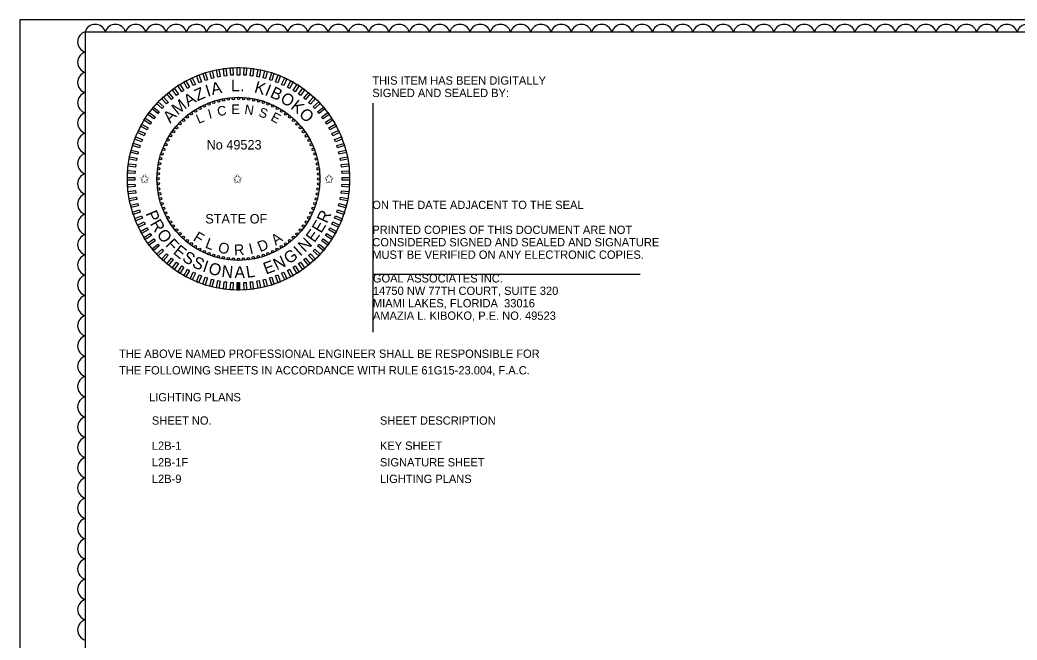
# Model space of a CAD drawing. Extents: x -816.9 to -790.1, y -2199.5 to -2188.9.
# Drawn here: x -811.34 to -802.91, y -2194.13 to -2188.9 of the extents above; entities that cross this region are included whole.
import ezdxf

# ---------------------------------------------------------------- set-up
doc = ezdxf.new("R2010")
doc.units = 0
for name, color, linetype in [('Cloud_dp', 7, 'Continuous'), ('Logo_dp', 7, 'Continuous'), ('NonPlottingEle_dp', 7, 'Continuous'), ('PlotBorder_dp', 7, 'Continuous'), ('ScratchEle_dp', 7, 'Continuous'), ('SheetBorder_dp', 7, 'Continuous'), ('TextMisc', 7, 'Continuous'), ('TextNotes', 7, 'Continuous')]:
    doc.layers.add(name, color=color, linetype=linetype)

msp = doc.modelspace()

# ---------------------------------------------------------------- linework, layer by layer
at = {"layer": 'Cloud_dp'}
for centre, start, end in [((-810.7002, -2189.0276), 17.5, 162.5), ((-810.5291, -2189.0276), 17.5, 162.5), ((-810.358, -2189.0276), 17.5, 162.5), ((-810.1868, -2189.0276), 17.5, 162.5), ((-810.0157, -2189.0276), 17.5, 162.5), ((-809.8446, -2189.0276), 17.5, 162.5), ((-809.6735, -2189.0276), 17.5, 162.5), ((-809.5024, -2189.0276), 17.5, 162.5), ((-809.3312, -2189.0276), 17.5, 162.5), ((-809.1601, -2189.0276), 17.5, 162.5), ((-808.989, -2189.0276), 17.5, 162.5), ((-808.8179, -2189.0276), 17.5, 162.5), ((-808.6467, -2189.0276), 17.5, 162.5), ((-808.4756, -2189.0276), 17.5, 162.5), ((-808.3045, -2189.0276), 17.5, 162.5), ((-808.1334, -2189.0276), 17.5, 162.5), ((-807.9622, -2189.0276), 17.5, 162.5), ((-807.7911, -2189.0276), 17.5, 162.5), ((-807.62, -2189.0276), 17.5, 162.5), ((-807.4489, -2189.0276), 17.5, 162.5), ((-807.2778, -2189.0276), 17.5, 162.5), ((-807.1066, -2189.0276), 17.5, 162.5), ((-806.9355, -2189.0276), 17.5, 162.5), ((-806.7644, -2189.0276), 17.5, 162.5), ((-806.5933, -2189.0276), 17.5, 162.5), ((-806.4221, -2189.0276), 17.5, 162.5), ((-806.251, -2189.0276), 17.5, 162.5), ((-806.0799, -2189.0276), 17.5, 162.5), ((-805.9088, -2189.0276), 17.5, 162.5), ((-805.7377, -2189.0276), 17.5, 162.5), ((-805.5665, -2189.0276), 17.5, 162.5), ((-805.3954, -2189.0276), 17.5, 162.5), ((-805.2243, -2189.0276), 17.5, 162.5), ((-805.0532, -2189.0276), 17.5, 162.5), ((-804.882, -2189.0276), 17.5, 162.5), ((-804.7109, -2189.0276), 17.5, 162.5), ((-804.5398, -2189.0276), 17.5, 162.5), ((-804.3687, -2189.0276), 17.5, 162.5), ((-804.1976, -2189.0276), 17.5, 162.5), ((-804.0264, -2189.0276), 17.5, 162.5), ((-803.8553, -2189.0276), 17.5, 162.5), ((-803.6842, -2189.0276), 17.5, 162.5), ((-803.5131, -2189.0276), 17.5, 162.5), ((-803.3419, -2189.0276), 17.5, 162.5), ((-803.1708, -2189.0276), 17.5, 162.5), ((-802.9997, -2189.0276), 17.5, 162.5), ((-802.8286, -2189.0276), 17.5, 162.5), ((-810.7588, -2189.0862), 107.5, 252.5), ((-810.7588, -2189.2573), 107.5, 252.5), ((-810.7588, -2189.4284), 107.5, 252.5), ((-810.7588, -2189.5996), 107.5, 252.5), ((-810.7588, -2189.7707), 107.5, 252.5), ((-810.7588, -2189.9418), 107.5, 252.5), ((-810.7588, -2190.1129), 107.5, 252.5), ((-810.7588, -2190.2841), 107.5, 252.5), ((-810.7588, -2190.4552), 107.5, 252.5), ((-810.7588, -2190.6263), 107.5, 252.5), ((-810.7588, -2190.7974), 107.5, 252.5), ((-810.7588, -2190.9685), 107.5, 252.5), ((-810.7588, -2191.1397), 107.5, 252.5), ((-810.7588, -2191.3108), 107.5, 252.5), ((-810.7588, -2191.4819), 107.5, 252.5), ((-810.7588, -2191.653), 107.5, 252.5), ((-810.7588, -2191.8242), 107.5, 252.5), ((-810.7588, -2191.9953), 107.5, 252.5), ((-810.7588, -2192.1664), 107.5, 252.5), ((-810.7588, -2192.3375), 107.5, 252.5), ((-810.7588, -2192.5087), 107.5, 252.5), ((-810.7588, -2192.6798), 107.5, 252.5), ((-810.7588, -2192.8509), 107.5, 252.5), ((-810.7588, -2193.022), 107.5, 252.5), ((-810.7588, -2193.1931), 107.5, 252.5), ((-810.7588, -2193.3643), 107.5, 252.5), ((-810.7588, -2193.5354), 107.5, 252.5), ((-810.7588, -2193.7065), 107.5, 252.5), ((-810.7588, -2193.8776), 107.5, 252.5), ((-810.7588, -2194.0488), 107.5, 252.5)]:
    msp.add_arc(centre, 0.0897, start, end, dxfattribs=at)
at = {"layer": 'Logo_dp'}
for p, q in [((-809.5, -2191.1804), (-809.5002, -2191.1179)), ((-809.49, -2191.1804), (-809.4902, -2191.1178)), ((-809.48, -2191.1804), (-809.4802, -2191.1178))]:
    msp.add_line(p, q, dxfattribs=at)
for points in [[(-809.8031, -2189.4233), (-809.8219, -2189.4307), (-809.8449, -2189.3726), (-809.8261, -2189.3652)], [(-809.7511, -2189.4052), (-809.7703, -2189.4115), (-809.7896, -2189.352), (-809.7704, -2189.3458)], [(-809.698, -2189.3905), (-809.7176, -2189.3955), (-809.7332, -2189.335), (-809.7136, -2189.3299)], [(-809.6442, -2189.3791), (-809.664, -2189.3829), (-809.6758, -2189.3215), (-809.6559, -2189.3177)], [(-809.5897, -2189.3711), (-809.6098, -2189.3737), (-809.6176, -2189.3116), (-809.5976, -2189.3091)], [(-809.5349, -2189.3666), (-809.555, -2189.3679), (-809.559, -2189.3055), (-809.5388, -2189.3042)], [(-809.4798, -2189.3655), (-809.5, -2189.3655), (-809.5, -2189.303), (-809.4798, -2189.303)], [(-809.4248, -2189.3679), (-809.445, -2189.3666), (-809.4411, -2189.3042), (-809.4209, -2189.3055)], [(-809.3701, -2189.3737), (-809.3901, -2189.3712), (-809.3823, -2189.3091), (-809.3623, -2189.3117)], [(-809.3158, -2189.3829), (-809.3357, -2189.3792), (-809.324, -2189.3177), (-809.3041, -2189.3215)], [(-809.2623, -2189.3956), (-809.2818, -2189.3905), (-809.2663, -2189.33), (-809.2467, -2189.335)], [(-809.2096, -2189.4115), (-809.2288, -2189.4053), (-809.2095, -2189.3458), (-809.1903, -2189.3521)], [(-809.158, -2189.4308), (-809.1768, -2189.4234), (-809.1538, -2189.3652), (-809.135, -2189.3727)], [(-809.9509, -2189.4964), (-809.968, -2189.5073), (-810.0015, -2189.4545), (-809.9844, -2189.4437)], [(-809.9032, -2189.469), (-809.9209, -2189.4787), (-809.951, -2189.4239), (-809.9333, -2189.4142)], [(-809.8539, -2189.4446), (-809.8721, -2189.4532), (-809.8988, -2189.3966), (-809.8805, -2189.388)], [(-809.1077, -2189.4532), (-809.126, -2189.4446), (-809.0994, -2189.3881), (-809.0811, -2189.3967)], [(-809.059, -2189.4788), (-809.0767, -2189.4691), (-809.0466, -2189.4143), (-809.0289, -2189.424)], [(-809.0119, -2189.5074), (-809.029, -2189.4965), (-808.9955, -2189.4438), (-808.9784, -2189.4546)], [(-810.0407, -2189.5601), (-810.0562, -2189.573), (-810.0961, -2189.5248), (-810.0805, -2189.5119)], [(-809.9968, -2189.5268), (-810.0131, -2189.5387), (-810.0499, -2189.4881), (-810.0335, -2189.4763)], [(-808.9668, -2189.5388), (-808.9831, -2189.527), (-808.9464, -2189.4764), (-808.93, -2189.4883)], [(-808.9237, -2189.5731), (-808.9392, -2189.5602), (-808.8994, -2189.512), (-808.8838, -2189.5249)], [(-810.1217, -2189.6345), (-810.1356, -2189.6492), (-810.1812, -2189.6064), (-810.1673, -2189.5917)], [(-810.0824, -2189.596), (-810.0971, -2189.6098), (-810.1399, -2189.5643), (-810.1252, -2189.5504)], [(-808.8828, -2189.61), (-808.8975, -2189.5961), (-808.8547, -2189.5505), (-808.84, -2189.5644)], [(-808.8443, -2189.6493), (-808.8582, -2189.6346), (-808.8126, -2189.5918), (-808.7988, -2189.6065)], [(-810.1929, -2189.7184), (-810.2048, -2189.7348), (-810.2553, -2189.698), (-810.2435, -2189.6817)], [(-810.1586, -2189.6753), (-810.1715, -2189.6909), (-810.2197, -2189.6511), (-810.2068, -2189.6355)], [(-808.8084, -2189.691), (-808.8213, -2189.6755), (-808.7731, -2189.6356), (-808.7602, -2189.6512)], [(-808.7752, -2189.7349), (-808.7871, -2189.7186), (-808.7365, -2189.6818), (-808.7246, -2189.6982)], [(-810.2529, -2189.8106), (-810.2626, -2189.8284), (-810.3174, -2189.7982), (-810.3077, -2189.7805)], [(-810.2243, -2189.7636), (-810.2352, -2189.7807), (-810.288, -2189.7472), (-810.2771, -2189.7301)], [(-808.7448, -2189.7808), (-808.7556, -2189.7638), (-808.7028, -2189.7303), (-808.692, -2189.7473)], [(-808.7173, -2189.8285), (-808.7271, -2189.8108), (-808.6723, -2189.7807), (-808.6625, -2189.7984)], [(-810.2785, -2189.8594), (-810.2871, -2189.8777), (-810.3436, -2189.8511), (-810.335, -2189.8328)], [(-808.6929, -2189.8779), (-808.7015, -2189.8596), (-808.6449, -2189.8329), (-808.6363, -2189.8512)], [(-810.3202, -2189.9612), (-810.3264, -2189.9805), (-810.3859, -2189.9611), (-810.3796, -2189.9419)], [(-810.3009, -2189.9097), (-810.3084, -2189.9285), (-810.3665, -2189.9054), (-810.359, -2189.8866)], [(-808.6716, -2189.9286), (-808.6791, -2189.9098), (-808.6209, -2189.8868), (-808.6135, -2189.9056)], [(-808.6536, -2189.9806), (-808.6598, -2189.9614), (-808.6004, -2189.9421), (-808.5941, -2189.9613)], [(-810.3361, -2190.0139), (-810.3412, -2190.0335), (-810.4017, -2190.0179), (-810.3967, -2189.9984)], [(-808.6388, -2190.0337), (-808.6439, -2190.0141), (-808.5833, -2189.9985), (-808.5783, -2190.0181)], [(-810.358, -2190.1218), (-810.3605, -2190.1418), (-810.4226, -2190.134), (-810.42, -2190.1139)], [(-810.3488, -2190.0675), (-810.3526, -2190.0873), (-810.414, -2190.0756), (-810.4102, -2190.0558)], [(-808.6275, -2190.0875), (-808.6312, -2190.0677), (-808.5698, -2190.056), (-808.566, -2190.0758)], [(-808.6195, -2190.142), (-808.622, -2190.1219), (-808.56, -2190.1141), (-808.5575, -2190.1342)], [(-810.3638, -2190.1765), (-810.3651, -2190.1967), (-810.4275, -2190.1927), (-810.4262, -2190.1726)], [(-808.6149, -2190.1968), (-808.6162, -2190.1767), (-808.5538, -2190.1727), (-808.5525, -2190.1929)], [(-810.3662, -2190.2315), (-810.3662, -2190.2517), (-810.4287, -2190.2517), (-810.4287, -2190.2315)], [(-810.3651, -2190.2865), (-810.3638, -2190.3067), (-810.4262, -2190.3106), (-810.4275, -2190.2904)], [(-808.6162, -2190.3069), (-808.615, -2190.2867), (-808.5526, -2190.2906), (-808.5538, -2190.3108)], [(-808.6139, -2190.2519), (-808.6139, -2190.2317), (-808.5513, -2190.2317), (-808.5513, -2190.2519)], [(-810.3606, -2190.3414), (-810.358, -2190.3614), (-810.4201, -2190.3693), (-810.4226, -2190.3492)], [(-808.622, -2190.3616), (-808.6195, -2190.3416), (-808.5575, -2190.3494), (-808.56, -2190.3695)], [(-810.3526, -2190.3958), (-810.3488, -2190.4157), (-810.4102, -2190.4274), (-810.414, -2190.4076)], [(-810.3412, -2190.4497), (-810.3362, -2190.4693), (-810.3967, -2190.4848), (-810.4018, -2190.4652)], [(-808.6439, -2190.4695), (-808.6389, -2190.4499), (-808.5783, -2190.4654), (-808.5834, -2190.485)], [(-808.6313, -2190.4159), (-808.6275, -2190.396), (-808.5661, -2190.4077), (-808.5699, -2190.4276)], [(-810.3265, -2190.5027), (-810.3202, -2190.522), (-810.3797, -2190.5413), (-810.3859, -2190.5221)], [(-808.6599, -2190.5221), (-808.6536, -2190.5029), (-808.5942, -2190.5222), (-808.6004, -2190.5415)], [(-810.3084, -2190.5547), (-810.301, -2190.5735), (-810.3591, -2190.5966), (-810.3666, -2190.5778)], [(-810.2872, -2190.6055), (-810.2785, -2190.6238), (-810.3351, -2190.6504), (-810.3437, -2190.6321)], [(-808.7016, -2190.624), (-808.693, -2190.6057), (-808.6364, -2190.6323), (-808.645, -2190.6506)], [(-808.6791, -2190.5737), (-808.6717, -2190.5549), (-808.6136, -2190.5779), (-808.621, -2190.5967)], [(-810.2627, -2190.6548), (-810.253, -2190.6726), (-810.3078, -2190.7027), (-810.3175, -2190.685)], [(-810.2353, -2190.7026), (-810.2244, -2190.7196), (-810.2772, -2190.7531), (-810.2881, -2190.7361)], [(-808.7557, -2190.7198), (-808.7449, -2190.7027), (-808.6921, -2190.7362), (-808.7029, -2190.7533)], [(-808.7271, -2190.6727), (-808.7174, -2190.655), (-808.6626, -2190.6851), (-808.6724, -2190.7028)], [(-810.2049, -2190.7484), (-810.193, -2190.7648), (-810.2436, -2190.8015), (-810.2554, -2190.7852)], [(-810.1716, -2190.7923), (-810.1587, -2190.8079), (-810.2069, -2190.8477), (-810.2198, -2190.8322)], [(-808.8214, -2190.808), (-808.8085, -2190.7925), (-808.7604, -2190.8323), (-808.7732, -2190.8479)], [(-808.7872, -2190.7649), (-808.7753, -2190.7486), (-808.7247, -2190.7853), (-808.7366, -2190.8017)], [(-810.1357, -2190.834), (-810.1219, -2190.8488), (-810.1675, -2190.8916), (-810.1813, -2190.8768)], [(-810.0972, -2190.8734), (-810.0825, -2190.8872), (-810.1253, -2190.9328), (-810.14, -2190.919)], [(-808.8977, -2190.8874), (-808.8829, -2190.8735), (-808.8401, -2190.9191), (-808.8549, -2190.9329)], [(-808.8583, -2190.8489), (-808.8445, -2190.8342), (-808.7989, -2190.877), (-808.8127, -2190.8917)], [(-810.0564, -2190.9103), (-810.0408, -2190.9232), (-810.0807, -2190.9713), (-810.0962, -2190.9585)], [(-810.0133, -2190.9445), (-809.9969, -2190.9564), (-810.0337, -2191.007), (-810.05, -2190.9951)], [(-808.9833, -2190.9565), (-808.9669, -2190.9446), (-808.9302, -2190.9952), (-808.9465, -2191.0071)], [(-808.9394, -2190.9233), (-808.9238, -2190.9104), (-808.884, -2190.9586), (-808.8995, -2190.9715)], [(-809.9681, -2190.976), (-809.951, -2190.9868), (-809.9845, -2191.0396), (-810.0016, -2191.0288)], [(-809.9211, -2191.0046), (-809.9034, -2191.0143), (-809.9335, -2191.0691), (-809.9512, -2191.0594)], [(-809.8723, -2191.0301), (-809.854, -2191.0387), (-809.8806, -2191.0953), (-809.8989, -2191.0867)], [(-809.822, -2191.0526), (-809.8033, -2191.06), (-809.8263, -2191.1181), (-809.8451, -2191.1107)], [(-809.177, -2191.0601), (-809.1582, -2191.0526), (-809.1352, -2191.1108), (-809.154, -2191.1182)], [(-809.1262, -2191.0388), (-809.1079, -2191.0302), (-809.0813, -2191.0868), (-809.0996, -2191.0954)], [(-809.0769, -2191.0144), (-809.0592, -2191.0047), (-809.029, -2191.0594), (-809.0467, -2191.0692)], [(-809.0292, -2190.9869), (-809.0121, -2190.9761), (-808.9786, -2191.0289), (-808.9957, -2191.0397)], [(-809.7705, -2191.0718), (-809.7513, -2191.0781), (-809.7706, -2191.1375), (-809.7898, -2191.1313)], [(-809.7178, -2191.0878), (-809.6982, -2191.0928), (-809.7138, -2191.1534), (-809.7333, -2191.1484)], [(-809.6642, -2191.1004), (-809.6444, -2191.1042), (-809.6561, -2191.1656), (-809.6759, -2191.1618)], [(-809.61, -2191.1097), (-809.5899, -2191.1122), (-809.5977, -2191.1742), (-809.6178, -2191.1717)], [(-809.5552, -2191.1155), (-809.535, -2191.1168), (-809.539, -2191.1792), (-809.5591, -2191.1779)], [(-809.5002, -2191.1179), (-809.48, -2191.1179), (-809.48, -2191.1804), (-809.5002, -2191.1804)], [(-809.4452, -2191.1168), (-809.425, -2191.1155), (-809.4211, -2191.1779), (-809.4413, -2191.1792)], [(-809.3903, -2191.1122), (-809.3703, -2191.1097), (-809.3624, -2191.1717), (-809.3825, -2191.1743)], [(-809.3359, -2191.1043), (-809.316, -2191.1005), (-809.3043, -2191.1619), (-809.3241, -2191.1657)], [(-809.282, -2191.0929), (-809.2624, -2191.0878), (-809.2469, -2191.1484), (-809.2665, -2191.1534)], [(-809.229, -2191.0781), (-809.2097, -2191.0719), (-809.1904, -2191.1313), (-809.2097, -2191.1376)]]:
    msp.add_lwpolyline(points, close=True, dxfattribs=at)
for centre in [(-809.7783, -2189.6277), (-809.7392, -2189.6108), (-809.6991, -2189.5964), (-809.6582, -2189.5845), (-809.6166, -2189.5752), (-809.5745, -2189.5686), (-809.5321, -2189.5646), (-809.4895, -2189.5633), (-809.4469, -2189.5647), (-809.4044, -2189.5687), (-809.3624, -2189.5755), (-809.3208, -2189.5848), (-809.2799, -2189.5967), (-809.2398, -2189.6112), (-809.2007, -2189.6281), (-809.922, -2189.7186), (-809.8883, -2189.6926), (-809.853, -2189.6686), (-809.8163, -2189.647), (-809.1627, -2189.6475), (-809.1261, -2189.6692), (-809.0908, -2189.6932), (-809.9841, -2189.7769), (-809.954, -2189.7468), (-809.0572, -2189.7194), (-809.0252, -2189.7476), (-808.9951, -2189.7777), (-810.0625, -2189.8777), (-810.0385, -2189.8425), (-810.0123, -2189.8088), (-808.967, -2189.8097), (-808.9409, -2189.8434), (-808.917, -2189.8787), (-810.1036, -2189.9523), (-810.0842, -2189.9144), (-808.8953, -2189.9154), (-808.876, -2189.9534), (-810.135, -2190.0315), (-810.1205, -2189.9914), (-808.8591, -2189.9925), (-808.8447, -2190.0326), (-810.1563, -2190.114), (-810.1469, -2190.0724), (-808.8328, -2190.0735), (-808.8236, -2190.1151), (-810.167, -2190.1985), (-810.163, -2190.1561), (-808.8169, -2190.1572), (-808.813, -2190.1997), (-810.1684, -2190.2411), (-810.1671, -2190.2837), (-808.813, -2190.2848), (-808.8117, -2190.2422), (-810.1631, -2190.3261), (-810.1565, -2190.3682), (-808.8238, -2190.3693), (-808.8171, -2190.3273), (-810.1472, -2190.4098), (-810.1354, -2190.4508), (-808.845, -2190.4518), (-808.8331, -2190.4109), (-810.121, -2190.4909), (-810.1041, -2190.53), (-808.8765, -2190.531), (-808.8595, -2190.4919), (-810.0847, -2190.568), (-810.0631, -2190.6047), (-810.0392, -2190.64), (-808.9416, -2190.6409), (-808.9176, -2190.6056), (-808.8959, -2190.569), (-810.0131, -2190.6736), (-809.9849, -2190.7056), (-808.9959, -2190.7065), (-808.9677, -2190.6745), (-809.9548, -2190.7358), (-809.9229, -2190.764), (-809.8892, -2190.7902), (-809.0918, -2190.7908), (-809.0581, -2190.7647), (-809.0261, -2190.7366), (-809.854, -2190.8141), (-809.8173, -2190.8359), (-809.7794, -2190.8552), (-809.7403, -2190.8722), (-809.7002, -2190.8867), (-809.2809, -2190.887), (-809.2408, -2190.8726), (-809.2017, -2190.8557), (-809.1637, -2190.8364), (-809.127, -2190.8147), (-809.6593, -2190.8986), (-809.6177, -2190.9079), (-809.5756, -2190.9146), (-809.5332, -2190.9187), (-809.49, -2190.9201), (-809.448, -2190.9187), (-809.4056, -2190.9148), (-809.3635, -2190.9081), (-809.3219, -2190.8989)]:
    msp.add_circle(centre, 0.01, dxfattribs=at)
at = {"layer": 'NonPlottingEle_dp'}
for radius in [0.9387, 0.6884]:
    msp.add_circle((-809.49, -2190.2417), radius, dxfattribs=at)
at = {"layer": 'PlotBorder_dp'}
msp.add_lwpolyline([(-811.3358, -2199.5006), (-794.8358, -2199.5006), (-794.8358, -2188.9006), (-811.3358, -2188.9006)], close=True, dxfattribs=at)
at = {"layer": 'ScratchEle_dp'}
for p, q in [((-808.3546, -2189.6017), (-808.3546, -2191.5365)), ((-808.3546, -2191.0465), (-806.0979, -2191.0465))]:
    msp.add_line(p, q, dxfattribs=at)
at = {"layer": 'SheetBorder_dp'}
for q in [(-810.7858, -2199.4006), (-795.3858, -2189.0006)]:
    msp.add_line((-810.7858, -2189.0006), q, dxfattribs=at)

# ---------------------------------------------------------------- texts
at = {"layer": 'Logo_dp'}
for s, rotation, p in [('C', 8.98261, (-809.6632, -2189.7131)), ('E', 359.96623, (-809.5504, -2189.6942)), ('N', 350.64643, (-809.4434, -2189.6927)), ('L', 23.30524, (-809.8266, -2189.7788)), ('I', 14.81888, (-809.7359, -2189.7358)), ('S', 341.03996, (-809.3261, -2189.7116)), ('E', 331.16864, (-809.2245, -2189.7442))]:
    msp.add_text(s, height=0.0801, rotation=rotation, dxfattribs=at).set_placement(p)
for p in [(-810.3261, -2190.2797), (-809.5404, -2190.2797), (-808.7675, -2190.2797)]:
    msp.add_text('✩', height=0.0801, dxfattribs=at).set_placement(p)
at = {"layer": 'TextMisc'}
for s, height, rotation, p in [('I', 0.1001, 17.68363, (-809.7505, -2189.5498)), ('A', 0.1001, 11.91844, (-809.7111, -2189.5338)), ('L', 0.1001, 359.96623, (-809.5537, -2189.5034)), ('K', 0.1001, 344.27273, (-809.3628, -2189.5106)), ('I', 0.1001, 337.77772, (-809.2741, -2189.5325)), ('A', 0.1001, 31.46601, (-809.9149, -2189.6362)), ('Z', 0.1001, 23.30524, (-809.8374, -2189.5875)), ('.', 0.1001, 353.78581, (-809.4769, -2189.5005)), ('B', 0.1001, 334.48695, (-809.23, -2189.5478)), ('O', 0.1001, 327.82385, (-809.1453, -2189.5865)), ('M', 0.1001, 39.30005, (-810.0041, -2189.7084)), ('K', 0.1001, 321.0594, (-809.0556, -2189.6437)), ('A', 0.1001, 46.80938, (-810.0664, -2189.777)), ('O', 0.1001, 314.20329, (-808.9858, -2189.7014)), ('P', 0.1002, 293.19548, (-810.2767, -2190.5336)), ('R', 0.1002, 65.28865, (-808.7427, -2190.6231)), ('R', 0.1002, 300.25949, (-810.2398, -2190.6197)), ('E', 0.1002, 58.61694, (-808.7919, -2190.7072)), ('O', 0.1002, 307.26617, (-810.1856, -2190.7116)), ('F', 0.0902, 328.53399, (-809.879, -2190.7577)), ('A', 0.0902, 35.54629, (-809.1752, -2190.807)), ('E', 0.1002, 53.99864, (-808.8492, -2190.786)), ('F', 0.1002, 314.20329, (-810.1121, -2190.8042)), ('E', 0.1002, 321.0594, (-810.0487, -2190.8679)), ('L', 0.0902, 339.48752, (-809.7776, -2190.8207)), ('O', 0.0902, 348.08156, (-809.668, -2190.8614)), ('R', 0.0902, 3.10738, (-809.5257, -2190.8876)), ('I', 0.0902, 12.52485, (-809.3913, -2190.8785)), ('D', 0.0902, 22.22228, (-809.3071, -2190.8616)), ('N', 0.1002, 44.34211, (-808.9294, -2190.866)), ('S', 0.1002, 327.82385, (-809.9723, -2190.9285)), ('G', 0.1002, 34.11362, (-809.0651, -2190.9664)), ('I', 0.1002, 41.83906, (-808.9688, -2190.9003)), ('S', 0.1002, 334.48695, (-809.8891, -2190.98)), ('I', 0.1002, 341.03996, (-809.8004, -2191.0213)), ('O', 0.1002, 344.27273, (-809.7512, -2191.0389)), ('N', 0.1002, 353.78581, (-809.6367, -2191.0689)), ('E', 0.1002, 20.51248, (-809.2581, -2191.0499)), ('N', 0.1002, 26.0618, (-809.1664, -2191.0166)), ('A', 0.1002, 359.96623, (-809.5242, -2191.0799)), ('L', 0.1002, 8.98261, (-809.4185, -2191.079))]:
    msp.add_text(s, height=height, rotation=rotation, dxfattribs=at).set_placement(p)
for s, height, p in [('THIS ITEM HAS BEEN DIGITALLY', 0.07, (-808.3596, -2189.4466)), ('SIGNED AND SEALED BY:', 0.07, (-808.3596, -2189.5516)), ('No 49523', 0.0801, (-809.7593, -2189.9941)), ('ON THE DATE ADJACENT TO THE SEAL', 0.07, (-808.3596, -2190.4966)), ('STATE OF', 0.0801, (-809.7701, -2190.6184)), ('PRINTED COPIES OF THIS DOCUMENT ARE NOT ', 0.07, (-808.3596, -2190.7066)), ('CONSIDERED SIGNED AND SEALED AND SIGNATURE ', 0.07, (-808.3596, -2190.8116)), ('MUST BE VERIFIED ON ANY ELECTRONIC COPIES.', 0.07, (-808.3596, -2190.9166)), ('GOAL ASSOCIATES INC.', 0.07, (-808.3546, -2191.1165)), ('14750 NW 77TH COURT, SUITE 320', 0.07, (-808.3546, -2191.2215)), ('MIAMI LAKES, FLORIDA  33016', 0.07, (-808.3546, -2191.3265)), ('AMAZIA L. KIBOKO, P.E. NO. 49523', 0.07, (-808.3546, -2191.4315)), ('THE ABOVE NAMED PROFESSIONAL ENGINEER SHALL BE RESPONSIBLE FOR ', 0.07, (-810.4987, -2191.7526)), ('THE FOLLOWING SHEETS IN ACCORDANCE WITH RULE 61G15-23.004, F.A.C.', 0.07, (-810.4987, -2191.8926)), ('LIGHTING PLANS', 0.07, (-810.245, -2192.1196))]:
    msp.add_text(s, height=height, dxfattribs=at).set_placement(p)
at = {"layer": 'TextNotes'}
for s, p in [('SHEET NO.', (-810.2215, -2192.3166)), ('SHEET DESCRIPTION', (-808.2953, -2192.3166)), ('L2B-1', (-810.2215, -2192.5288)), ('KEY SHEET', (-808.2953, -2192.5288)), ('L2B-1F', (-810.2215, -2192.6688)), ('SIGNATURE SHEET', (-808.2953, -2192.6688)), ('L2B-9', (-810.2215, -2192.8088)), ('LIGHTING PLANS', (-808.2953, -2192.8088))]:
    msp.add_text(s, height=0.07, dxfattribs=at).set_placement(p)

doc.saveas('drawing.dxf')
